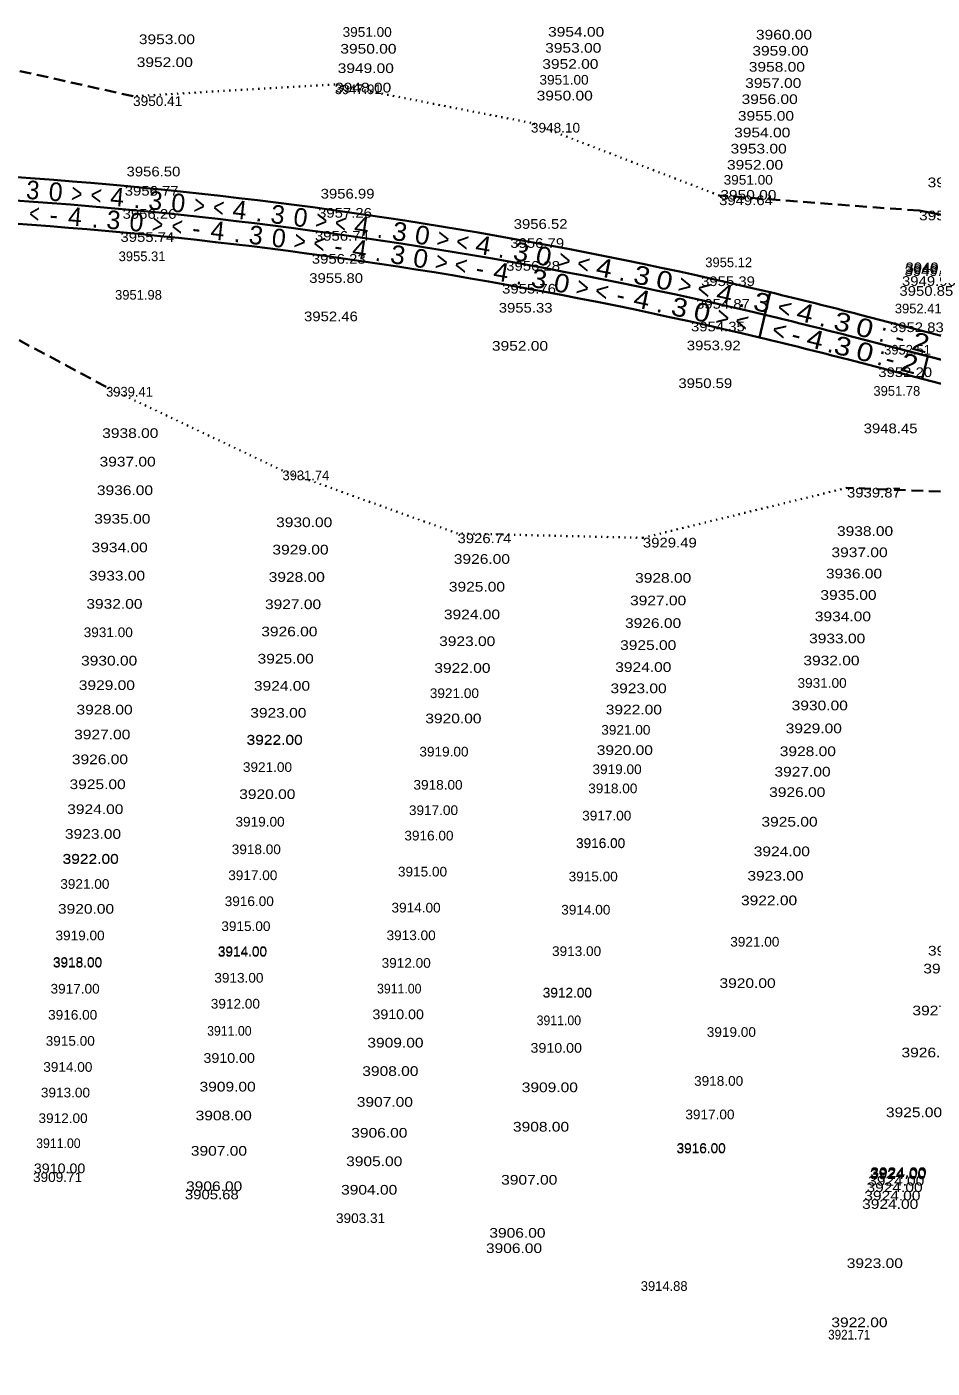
# Model space of a CAD drawing. Extents: x 49942 to 56479, y 47140 to 53283.
# Drawn here: x 54041 to 54509, y 49210 to 49903 of the extents above; entities that cross this region are included whole.
import ezdxf
from ezdxf.enums import TextEntityAlignment as Align

# ---------------------------------------------------------------- set-up
doc = ezdxf.new("R2010")
doc.units = 0
doc.header["$LTSCALE"] = 2
doc.linetypes.add('DOTTED', pattern=[1.5, 0.3, -1.2])
doc.linetypes.add('MEDIUM_DASHED', pattern=[4.5, 3, -1.5])
doc.layers.add('29', color=7, linetype='Continuous')
doc.layers.add('59', color=7, linetype='Continuous', lineweight=35)
doc.layers.add('63', color=7, linetype='Continuous', lineweight=35)

msp = doc.modelspace()

# ---------------------------------------------------------------- linework, layer by layer
at = {"layer": '59', "linetype": 'MEDIUM_DASHED'}
for p, q in [((54096.16, 49866.921), (53994.743, 49889.532)), ((54502.081, 49807.794), (54398.821, 49815.658)), ((54082.2, 49716.709), (53988.534, 49767.027)), ((54567.105, 49660.354), (54464.871, 49664.531))]:
    msp.add_line(p, q, dxfattribs=at)
at = {"layer": '59', "linetype": 'DOTTED'}
for p, q in [((54200.354, 49873.01), (54096.16, 49866.921)), ((54301.626, 49853.171), (54200.354, 49873.01)), ((54398.821, 49815.658), (54301.626, 49853.171)), ((54173.312, 49673.48), (54082.2, 49716.709)), ((54263.72, 49640.933), (54173.312, 49673.48)), ((54464.871, 49664.531), (54359.476, 49638.693)), ((54359.476, 49638.693), (54263.72, 49640.933))]:
    msp.add_line(p, q, dxfattribs=at)
at = {"layer": '59'}
msp.add_line((54600.525, 49789.026), (54502.081, 49807.794), dxfattribs=at)
at = {"layer": '63'}
for p, q in [((54425.226, 49765.587), (54422.442, 49753.915)), ((54422.442, 49753.915), (54425.226, 49765.587)), ((54419.658, 49742.242), (54422.442, 49753.915)), ((54422.442, 49753.915), (54419.658, 49742.242))]:
    msp.add_line(p, q, dxfattribs=at)
for points in [[(54471.664, 49754.021), (54656.01, 49706.141), (54652.993, 49694.526), (54468.647, 49742.406)], [(54465.631, 49730.791), (54503.671, 49720.911), (54506.687, 49732.526), (54468.647, 49742.406)]]:
    msp.add_lwpolyline(points, dxfattribs=at)
msp.add_lwpolyline([(54503.671, 49720.911), (56472.661, 49209.506), (56475.677, 49221.12), (54506.687, 49732.526)], close=True, dxfattribs=at)
for radius, start, end in [(2391.064, 76.58708, 91.33234), (2379.064, 76.58708, 91.33234), (2379.064, 76.58708, 91.33234), (2367.064, 76.58708, 91.33234), (2391.064, 75.44028, 76.58708), (2379.064, 75.44028, 76.58708), (2379.064, 75.44028, 76.58708), (2367.064, 75.44028, 76.58708)]:
    msp.add_arc((53870.577, 47439.743), radius, start, end, dxfattribs=at)

# ---------------------------------------------------------------- texts
at = {"layer": '29'}
for s, width, p in [('3953.00', 1.2, (54099.13, 49893.875)), ('3951.00', 1.05, (54204.37, 49897.641)), ('3954.00', 1.2, (54310.479, 49897.735)), ('3960.00', 1.2, (54417.85, 49896.245)), ('3950.00', 1.2, (54203.193, 49888.961)), ('3953.00', 1.2, (54308.994, 49889.423)), ('3959.00', 1.2, (54416.001, 49887.932)), ('3952.00', 1.2, (54098.03, 49882.038)), ('3949.00', 1.2, (54201.833, 49878.927)), ('3952.00', 1.2, (54307.509, 49881.11)), ('3958.00', 1.2, (54414.153, 49879.618)), ('3951.00', 1.05, (54306.05, 49872.936)), ('3957.00', 1.2, (54412.294, 49871.258)), ('3948.00', 1.2, (54200.474, 49868.893)), ('3950.00', 1.2, (54304.59, 49864.763)), ('3950.41', 1.05, (54096.16, 49861.921)), ('3956.00', 1.2, (54410.435, 49862.898)), ('3955.00', 1.2, (54408.521, 49854.286)), ('3948.10', 1.05, (54301.626, 49848.171)), ('3954.00', 1.2, (54406.606, 49845.675)), ('3953.00', 1.2, (54404.752, 49837.336)), ('3956.50', 1.15, (54092.775, 49825.503)), ('3952.00', 1.2, (54402.898, 49828.996)), ('3951.00', 1.05, (54401.17, 49821.224)), ('3958.00', 1.2, (54506.525, 49819.904)), ('3956.77', 1.15, (54091.85, 49815.546)), ('3956.99', 1.15, (54193.041, 49814.055)), ('3949.64', 1.15, (54398.821, 49810.658)), ('3950.00', 1.2, (54399.442, 49813.452)), ('3956.26', 1.15, (54090.74, 49803.598)), ('3957.26', 1.15, (54191.698, 49804.145)), ('3956.00', 1.2, (54502.081, 49802.794)), ('3956.52', 1.15, (54292.737, 49798.403)), ('3955.74', 1.15, (54089.629, 49791.649)), ('3956.74', 1.15, (54190.087, 49792.254)), ('3956.79', 1.15, (54290.979, 49788.559)), ('3956.23', 1.15, (54188.475, 49780.363)), ('3956.28', 1.15, (54288.869, 49776.746)), ('3949.08', 1.15, (54494.868, 49775.022)), ('3949.08', 1.15, (54495.119, 49775.99)), ('3955.80', 1.15, (54187.132, 49770.453)), ('3955.39', 1.15, (54389.518, 49768.814)), ('3949.96', 1.15, (54493.283, 49768.921)), ('3949.08', 1.15, (54494.617, 49774.055)), ('3955.76', 1.15, (54286.76, 49764.933)), ('3950.85', 1.15, (54491.95, 49763.788)), ('3955.33', 1.15, (54285.001, 49755.088)), ('3954.87', 1.15, (54386.913, 49757.1)), ('3952.46', 1.15, (54184.446, 49750.635)), ('3954.35', 1.15, (54384.309, 49745.386)), ('3952.83', 1.15, (54487.075, 49745.018)), ('3952.00', 1.2, (54281.485, 49735.4)), ('3953.92', 1.15, (54382.138, 49735.624)), ('3952.20', 1.15, (54481.042, 49721.789)), ('3950.59', 1.15, (54377.798, 49716.101)), ('3948.45', 1.15, (54473.5, 49692.752)), ('3938.00', 1.2, (54080.211, 49690.317)), ('3937.00', 1.2, (54078.839, 49675.552)), ('3936.00', 1.2, (54077.467, 49660.787)), ('3939.87', 1.15, (54464.871, 49659.531)), ('3935.00', 1.2, (54076.093, 49646.005)), ('3930.00', 1.2, (54170.026, 49644.232)), ('3926.74', 1.15, (54263.72, 49635.933)), ('3938.00', 1.2, (54459.716, 49639.681)), ('3934.00', 1.2, (54074.719, 49631.223)), ('3929.00', 1.2, (54168.107, 49630.077)), ('3929.49', 1.15, (54359.476, 49633.693)), ('3937.00', 1.2, (54456.863, 49628.697)), ('3926.00', 1.2, (54261.811, 49625.246)), ('3933.00', 1.2, (54073.363, 49616.631)), ('3928.00', 1.2, (54166.189, 49615.921)), ('3928.00', 1.2, (54355.424, 49615.47)), ('3936.00', 1.2, (54454.01, 49617.712)), ('3925.00', 1.2, (54259.252, 49610.919)), ('3932.00', 1.2, (54072.007, 49602.04)), ('3927.00', 1.2, (54164.28, 49601.842)), ('3927.00', 1.2, (54352.83, 49603.802)), ('3935.00', 1.2, (54451.134, 49606.638)), ('3924.00', 1.2, (54256.693, 49596.591)), ('3934.00', 1.2, (54448.257, 49595.564)), ('3931.00', 1.05, (54070.643, 49587.365)), ('3926.00', 1.2, (54162.372, 49587.763)), ('3926.00', 1.2, (54350.232, 49592.115)), ('3923.00', 1.2, (54254.221, 49582.748)), ('3925.00', 1.2, (54347.704, 49580.748)), ('3933.00', 1.2, (54445.3, 49584.176)), ('3925.00', 1.2, (54160.469, 49573.717)), ('3930.00', 1.2, (54069.279, 49572.691)), ('3922.00', 1.2, (54251.748, 49568.906)), ('3924.00', 1.2, (54345.177, 49569.381)), ('3932.00', 1.2, (54442.342, 49572.788)), ('3929.00', 1.2, (54068.103, 49560.034)), ('3924.00', 1.2, (54158.565, 49559.671)), ('3931.00', 1.05, (54439.324, 49561.169)), ('3921.00', 1.05, (54249.42, 49555.869)), ('3923.00', 1.2, (54342.734, 49558.391)), ('3928.00', 1.2, (54066.926, 49547.377)), ('3923.00', 1.2, (54156.679, 49545.757)), ('3922.00', 1.2, (54340.29, 49547.401)), ('3930.00', 1.2, (54436.306, 49549.549)), ('3920.00', 1.2, (54247.091, 49542.832)), ('3927.00', 1.2, (54065.732, 49534.529)), ('3922.00', 1.2, (54154.769, 49531.663)), ('3922.00', 1.2, (54154.782, 49531.755)), ('3922.00', 1.2, (54154.794, 49531.843)), ('3921.00', 1.05, (54337.963, 49536.932)), ('3929.00', 1.2, (54433.228, 49537.699)), ('3919.00', 1.05, (54244.028, 49525.68)), ('3920.00', 1.2, (54335.635, 49526.464)), ('3928.00', 1.2, (54430.15, 49525.85)), ('3926.00', 1.2, (54064.538, 49521.681)), ('3921.00', 1.05, (54152.874, 49517.679)), ('3919.00', 1.05, (54333.436, 49516.571)), ('3927.00', 1.2, (54427.411, 49515.303)), ('3925.00', 1.2, (54063.342, 49508.811)), ('3918.00', 1.05, (54240.964, 49508.527)), ('3918.00', 1.05, (54331.236, 49506.678)), ('3926.00', 1.2, (54424.672, 49504.755)), ('3920.00', 1.2, (54150.979, 49503.695)), ('3924.00', 1.2, (54062.146, 49495.94)), ('3917.00', 1.05, (54238.62, 49495.401)), ('3917.00', 1.05, (54328.106, 49492.599)), ('3923.00', 1.2, (54060.955, 49483.124)), ('3919.00', 1.05, (54149.047, 49489.441)), ('3925.00', 1.2, (54420.695, 49489.444)), ('3916.00', 1.05, (54236.275, 49482.275)), ('3916.00', 1.05, (54324.932, 49478.322)), ('3916.00', 1.05, (54324.945, 49478.384)), ('3916.00', 1.05, (54324.959, 49478.445)), ('3922.00', 1.2, (54059.747, 49470.126)), ('3922.00', 1.2, (54059.755, 49470.22)), ('3922.00', 1.2, (54059.763, 49470.307)), ('3918.00', 1.05, (54147.115, 49475.188)), ('3924.00', 1.2, (54416.718, 49474.132)), ('3915.00', 1.05, (54232.95, 49463.653)), ('3921.00', 1.05, (54058.551, 49457.266)), ('3917.00', 1.05, (54145.297, 49461.769)), ('3915.00', 1.05, (54321.111, 49461.139)), ('3923.00', 1.2, (54413.438, 49461.503)), ('3916.00', 1.05, (54143.478, 49448.351)), ('3922.00', 1.2, (54410.135, 49448.786)), ('3920.00', 1.2, (54057.356, 49444.406)), ('3914.00', 1.05, (54229.624, 49445.032)), ('3914.00', 1.05, (54317.291, 49443.956)), ('3915.00', 1.05, (54141.73, 49435.451)), ('3919.00', 1.05, (54056.079, 49430.669)), ('3913.00', 1.05, (54227.072, 49430.746)), ('3914.00', 1.05, (54139.932, 49422.186)), ('3914.00', 1.05, (54139.957, 49422.369)), ('3914.00', 1.05, (54139.982, 49422.552)), ('3913.00', 1.05, (54312.534, 49422.562)), ('3921.00', 1.05, (54404.582, 49427.409)), ('3929.00', 1.2, (54506.7, 49422.789)), ('3918.00', 1.05, (54054.772, 49416.602)), ('3918.00', 1.05, (54054.787, 49416.766)), ('3918.00', 1.05, (54054.802, 49416.93)), ('3912.00', 1.05, (54224.521, 49416.46)), ('3913.00', 1.05, (54138.115, 49408.781)), ('3928.00', 1.2, (54504.296, 49413.533)), ('3917.00', 1.05, (54053.52, 49403.125)), ('3911.00', 0.95, (54222.149, 49403.181)), ('3912.00', 1.05, (54307.746, 49401.025)), ('3912.00', 1.05, (54307.766, 49401.116)), ('3912.00', 1.05, (54307.778, 49401.168)), ('3920.00', 1.2, (54399.03, 49406.033)), ('3912.00', 1.05, (54136.298, 49395.375)), ('3916.00', 1.05, (54052.267, 49389.648)), ('3910.00', 1.1, (54219.777, 49389.902)), ('3911.00', 0.95, (54304.58, 49386.785)), ('3927.00', 1.2, (54498.675, 49391.889)), ('3911.00', 0.95, (54134.397, 49381.35)), ('3919.00', 1.05, (54392.463, 49380.749)), ('3915.00', 1.05, (54051.014, 49376.169)), ('3909.00', 1.2, (54217.158, 49375.236)), ('3910.00', 1.1, (54301.414, 49372.544)), ('3910.00', 1.1, (54132.497, 49367.324)), ('3926.00', 1.2, (54493.034, 49370.171)), ('3914.00', 1.05, (54049.762, 49362.691)), ('3908.00', 1.2, (54214.538, 49360.569)), ('3909.00', 1.2, (54130.488, 49352.506)), ('3909.00', 1.2, (54296.884, 49352.17)), ('3918.00', 1.05, (54385.896, 49355.465)), ('3913.00', 1.05, (54048.532, 49349.456)), ('3907.00', 1.2, (54211.689, 49344.617)), ('3908.00', 1.2, (54128.469, 49337.603)), ('3917.00', 1.05, (54381.401, 49338.159)), ('3925.00', 1.2, (54485.001, 49339.244)), ('3912.00', 1.05, (54047.301, 49336.221)), ('3908.00', 1.2, (54292.354, 49331.796)), ('3906.00', 1.2, (54208.84, 49328.666)), ('3911.00', 0.95, (54046.096, 49323.256)), ('3907.00', 1.2, (54125.992, 49319.327)), ('3916.00', 1.05, (54376.827, 49320.545)), ('3916.00', 1.05, (54376.863, 49320.684)), ('3916.00', 1.05, (54376.899, 49320.824)), ('3910.00', 1.1, (54044.89, 49310.275)), ('3905.00', 1.2, (54206.21, 49313.94)), ('3909.71', 1.05, (54044.469, 49305.744)), ('3907.00', 1.2, (54286.256, 49304.369)), ('3924.00', 1.2, (54475.815, 49303.874)), ('3924.00', 1.2, (54476.682, 49307.212)), ('3924.00', 1.2, (54476.825, 49307.765)), ('3924.00', 1.2, (54476.969, 49308.317)), ('3905.68', 1.15, (54122.936, 49296.784)), ('3906.00', 1.2, (54123.515, 49301.051)), ('3904.00', 1.2, (54203.58, 49299.215)), ('3924.00', 1.2, (54473.819, 49296.189)), ('3924.00', 1.2, (54474.947, 49300.535)), ('3924.00', 1.2, (54472.69, 49291.842)), ('3903.31', 1.05, (54200.958, 49284.535)), ('3906.00', 1.2, (54280.158, 49276.942)), ('3906.00', 1.2, (54278.397, 49269.018)), ('3923.00', 1.2, (54464.749, 49261.269)), ('3922.00', 1.2, (54456.808, 49230.695)), ('3921.71', 0.9, (54455.152, 49224.321))]:
    msp.add_text(s, height=5, dxfattribs=dict(at, width=width)).set_placement(p)
for s, p in [('3947.91', (54200.354, 49868.01)), ('3955.31', (54088.704, 49781.692)), ('3955.12', (54391.688, 49778.576)), ('3951.98', (54086.853, 49761.778)), ('3952.41', (54489.589, 49754.697)), ('3952.51', (54484.058, 49733.403)), ('3951.78', (54478.528, 49712.11)), ('3939.41', (54082.199, 49711.709)), ('3931.74', (54173.312, 49668.479)), ('3914.88', (54358.364, 49249.46))]:
    msp.add_text(s, height=5, dxfattribs=at).set_placement(p)
at = {"layer": '63'}
for s, rotation, width, p in [('3', 355.829, 0.95, (54044.063, 49813.673)), ('>', 355.283, 0.75, (54066.725, 49811.909)), ('<', 355.042, 0.75, (54076.711, 49811.063)), ('>', 353.758, 0.75, (54129.895, 49805.837)), ('<', 355.789, 0.7, (54044.85, 49801.584)), ('<', 353.517, 0.75, (54139.855, 49804.724)), ('>', 354.249, 0.75, (54108.39, 49796.035)), ('<', 354.005, 0.75, (54118.41, 49795.002)), ('>', 352.234, 0.8, (54192.882, 49798.083)), ('<', 351.993, 0.8, (54202.809, 49796.705)), ('4', 351.731, 1.05, (54213.616, 49795.155)), ('3', 351.255, 1.05, (54233.191, 49792.221)), ('0', 350.971, 1.05, (54244.862, 49790.392)), ('>', 352.465, 0.8, (54181.747, 49787.474)), ('<', 352.222, 0.8, (54191.73, 49786.129)), ('.', 351.493, 0.85, (54223.407, 49793.711)), ('>', 350.709, 0.85, (54255.641, 49788.652)), ('<', 350.468, 0.85, (54265.528, 49787.01)), ('4', 350.206, 1.1, (54276.29, 49785.172)), ('4', 351.714, 1.05, (54212.569, 49783.181)), ('3', 351.234, 1.05, (54232.242, 49780.225)), ('0', 350.947, 1.05, (54243.971, 49778.383)), ('3', 349.731, 1.1, (54295.78, 49781.717)), ('0', 349.447, 1.1, (54307.398, 49779.578)), ('.', 351.474, 0.85, (54222.409, 49781.726)), ('>', 350.682, 0.85, (54254.803, 49776.629)), ('<', 350.439, 0.85, (54264.739, 49774.974)), ('4', 349.931, 1.1, (54285.476, 49771.377)), ('.', 349.968, 0.9, (54286.039, 49783.468)), ('>', 349.185, 0.85, (54318.127, 49777.551)), ('<', 348.944, 0.85, (54327.967, 49775.646)), ('4', 348.681, 1.15, (54338.677, 49773.522)), ('3', 348.206, 1.15, (54358.068, 49769.549)), ('3', 349.451, 1.1, (54305.048, 49767.81)), ('0', 349.164, 1.1, (54316.714, 49765.602)), ('0', 347.922, 1.15, (54369.625, 49767.101)), ('>', 347.66, 0.9, (54380.296, 49764.788)), ('.', 349.691, 0.9, (54295.266, 49769.616)), ('>', 348.899, 0.85, (54327.486, 49763.511)), ('<', 348.656, 0.9, (54337.366, 49761.547)), ('4', 348.148, 1.15, (54357.982, 49757.306)), ('<', 347.419, 0.9, (54390.082, 49762.621)), ('4', 347.157, 1.15, (54400.732, 49760.212)), ('3', 346.681, 1.2, (54420.011, 49755.723)), ('3', 347.667, 1.15, (54377.433, 49753.13)), ('0', 347.381, 1.15, (54389.025, 49750.559)), ('<', 346.395, 0.95, (54431.615, 49752.941)), ('4', 346.133, 1.2, (54442.22, 49750.342)), ('>', 347.116, 0.9, (54399.727, 49748.133)), ('<', 346.873, 0.9, (54409.542, 49745.862)), ('3', 345.657, 1.2, (54461.416, 49745.508)), ('0', 345.454, 1.2, (54472.863, 49742.551)), ('<', 346.393, 0.95, (54428.871, 49741.259)), ('4', 345.932, 1.2, (54447.404, 49736.682)), ('2', 345.44, 1.2, (54501.791, 49735.037)), ('-', 346.173, 1.1, (54437.706, 49739.098)), ('3', 345.579, 1.2, (54461.59, 49733.073)), ('0', 345.44, 1.2, (54472.992, 49730.119)), ('-', 345.44, 1.1, (54491.198, 49737.789)), ('-', 345.44, 1.1, (54486.253, 49726.675)), ('2', 345.44, 1.2, (54495.902, 49724.169))]:
    msp.add_text(s, height=9.6, rotation=rotation, dxfattribs=dict(at, width=width)).set_placement(p, align=Align.CENTER)
for s, rotation, p in [('0', 355.545, (54055.842, 49812.783)), ('4', 354.78, (54087.585, 49810.091)), ('3', 354.304, (54107.288, 49808.204)), ('0', 354.02, (54119.04, 49807)), ('4', 355.28, (54065.831, 49799.941)), ('3', 354.8, (54085.649, 49798.218)), ('0', 354.513, (54097.47, 49797.11)), ('.', 354.542, (54097.99, 49809.118)), ('4', 353.255, (54150.7, 49803.463)), ('3', 352.78, (54170.346, 49801.052)), ('0', 352.496, (54182.061, 49799.535)), ('-', 355.545, (54054.893, 49800.822)), ('.', 355.04, (54076.335, 49799.051)), ('4', 353.497, (54139.33, 49792.705)), ('3', 353.017, (54159.085, 49790.365)), ('.', 353.017, (54160.947, 49802.229)), ('-', 353.762, (54128.425, 49793.926)), ('.', 353.257, (54149.651, 49791.506)), ('0', 352.73, (54170.866, 49788.889)), ('-', 351.979, (54201.707, 49784.742)), ('-', 350.196, (54274.668, 49773.276)), ('.', 348.444, (54348.377, 49771.558)), ('-', 348.413, (54347.238, 49759.54)), ('.', 346.919, (54410.376, 49757.99)), ('.', 347.907, (54367.712, 49755.24)), ('.', 345.895, (54451.824, 49747.947)), (':', 345.44, (54482.464, 49740.057)), ('.', 345.719, (54455.947, 49734.523)), (':', 345.44, (54481.498, 49727.91))]:
    msp.add_text(s, height=9.6, rotation=rotation, dxfattribs=at).set_placement(p, align=Align.CENTER)

doc.saveas('drawing.dxf')
